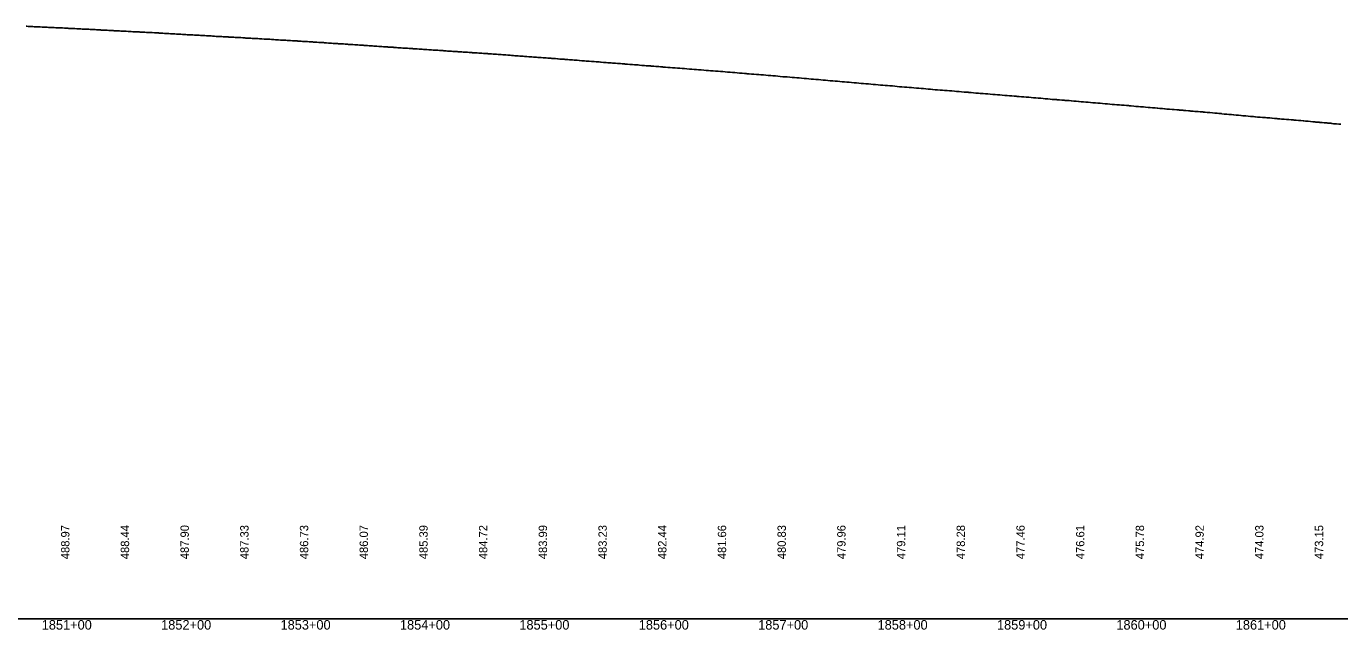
# Model space of a CAD drawing. Extents: x 2017200 to 2047700, y 854850 to 893350.
# Drawn here: x 2040063 to 2041163, y 856091 to 856597 of the extents above; entities that cross this region are included whole.
import ezdxf

# ---------------------------------------------------------------- set-up
doc = ezdxf.new("R2010")
doc.units = 0
for name, color, linetype in [('RD_DDB_Profile_EX', 7, 'Continuous'), ('RD_DDB_StaTX', 7, 'Continuous'), ('RD_DDB_StripGrade', 7, 'Continuous'), ('RD_GPK_Profile_Cell', 7, 'Continuous')]:
    doc.layers.add(name, color=color, linetype=linetype)

msp = doc.modelspace()

# ---------------------------------------------------------------- linework, layer by layer
at = {"layer": 'RD_DDB_Profile_EX'}
msp.add_lwpolyline([(2040062.7, 856596.7), (2040063.4, 856596.6), (2040064.4, 856596.5), (2040066.2, 856596.5), (2040067.6, 856596.4), (2040068.3, 856596.4), (2040069.5, 856596.3), (2040070.3, 856596.3), (2040071.3, 856596.2), (2040072.3, 856596.2), (2040072.9, 856596.2), (2040073.8, 856596.1), (2040074.6, 856596.1), (2040076.3, 856596), (2040077.7, 856595.9), (2040078.3, 856595.9), (2040079.6, 856595.8), (2040080.4, 856595.8), (2040081.4, 856595.7), (2040082.5, 856595.7), (2040083.1, 856595.7), (2040084.7, 856595.6), (2040086.3, 856595.5), (2040087.7, 856595.4), (2040088.4, 856595.4), (2040089.7, 856595.4), (2040090.5, 856595.3), (2040091.5, 856595.3), (2040092.6, 856595.2), (2040093.3, 856595.2), (2040094.8, 856595.1), (2040096.4, 856595), (2040097.8, 856595), (2040098.4, 856594.9), (2040099.7, 856594.9), (2040100.5, 856594.8), (2040101.6, 856594.8), (2040102.7, 856594.7), (2040103.5, 856594.7), (2040105.1, 856594.6), (2040106.4, 856594.5), (2040107.9, 856594.4), (2040108.5, 856594.4), (2040109.8, 856594.3), (2040110.6, 856594.3), (2040111.8, 856594.2), (2040112.7, 856594.2), (2040113.6, 856594.2), (2040115.3, 856594.1), (2040116.5, 856594), (2040117.9, 856593.9), (2040118.5, 856593.9), (2040119.9, 856593.8), (2040120.6, 856593.8), (2040121.8, 856593.7), (2040122.8, 856593.7), (2040123.7, 856593.6), (2040125.1, 856593.6), (2040125.5, 856593.5), (2040126.5, 856593.5), (2040128, 856593.4), (2040128.6, 856593.4), (2040130, 856593.3), (2040130.7, 856593.3), (2040131.9, 856593.2), (2040132.9, 856593.1), (2040133.9, 856593.1), (2040135.2, 856593), (2040135.7, 856593), (2040136.6, 856592.9), (2040138.1, 856592.8), (2040138.6, 856592.8), (2040140, 856592.7), (2040140.8, 856592.7), (2040142, 856592.6), (2040142.9, 856592.6), (2040144, 856592.5), (2040145.3, 856592.5), (2040145.9, 856592.5), (2040146.5, 856592.4), (2040148.1, 856592.3), (2040148.7, 856592.3), (2040150.1, 856592.2), (2040150.8, 856592.2), (2040152.1, 856592.1), (2040153, 856592.1), (2040154.1, 856592), (2040155.3, 856591.9), (2040156, 856591.9), (2040157.6, 856591.9), (2040158.1, 856591.8), (2040160.2, 856591.7), (2040161.6, 856591.6), (2040162.2, 856591.6), (2040163.5, 856591.5), (2040164.2, 856591.5), (2040165.3, 856591.4), (2040166.2, 856591.4), (2040166.9, 856591.3), (2040168.2, 856591.3), (2040170.2, 856591.1), (2040171.7, 856591.1), (2040172.2, 856591), (2040173.6, 856591), (2040174.2, 856590.9), (2040175.4, 856590.9), (2040176.3, 856590.8), (2040177.1, 856590.8), (2040178.5, 856590.7), (2040180.3, 856590.6), (2040181.7, 856590.5), (2040182.3, 856590.5), (2040183.7, 856590.4), (2040184.3, 856590.4), (2040185.5, 856590.3), (2040186.4, 856590.3), (2040187.3, 856590.2), (2040188.8, 856590.1), (2040190.3, 856590), (2040191.8, 856589.9), (2040192.3, 856589.9), (2040193.7, 856589.8), (2040194.4, 856589.8), (2040195.6, 856589.7), (2040196.5, 856589.7), (2040197.5, 856589.6), (2040198.6, 856589.6), (2040199, 856589.5), (2040200.3, 856589.5), (2040201.9, 856589.4), (2040202.4, 856589.4), (2040203.8, 856589.3), (2040204.4, 856589.2), (2040205.7, 856589.2), (2040206.5, 856589.1), (2040207.6, 856589.1), (2040208.7, 856589), (2040209.3, 856589), (2040210.4, 856588.9), (2040211.9, 856588.8), (2040212.4, 856588.8), (2040213.9, 856588.7), (2040214.5, 856588.7), (2040215.8, 856588.6), (2040216.6, 856588.6), (2040217.7, 856588.5), (2040218.8, 856588.4), (2040219.5, 856588.4), (2040220.4, 856588.3), (2040222, 856588.2), (2040222.5, 856588.2), (2040223.9, 856588.1), (2040224.5, 856588.1), (2040225.9, 856588), (2040226.7, 856588), (2040227.8, 856587.9), (2040228.9, 856587.8), (2040229.6, 856587.8), (2040230.4, 856587.7), (2040232, 856587.7), (2040232.5, 856587.6), (2040234, 856587.5), (2040234.6, 856587.5), (2040236, 856587.4), (2040236.7, 856587.4), (2040237.9, 856587.3), (2040239, 856587.3), (2040239.8, 856587.2), (2040240.5, 856587.2), (2040242.1, 856587.1), (2040242.5, 856587.1), (2040244.1, 856587), (2040244.6, 856586.9), (2040246, 856586.9), (2040246.7, 856586.8), (2040248, 856586.8), (2040249, 856586.7), (2040249.9, 856586.6), (2040250.9, 856586.6), (2040252.1, 856586.5), (2040252.5, 856586.5), (2040254.1, 856586.4), (2040254.6, 856586.4), (2040256.1, 856586.3), (2040256.8, 856586.3), (2040258.1, 856586.2), (2040259, 856586.1), (2040260, 856586.1), (2040262.2, 856585.9), (2040264.1, 856585.8), (2040264.7, 856585.8), (2040266.1, 856585.7), (2040266.8, 856585.7), (2040268.1, 856585.6), (2040269.1, 856585.5), (2040270.1, 856585.5), (2040271.7, 856585.4), (2040272.1, 856585.3), (2040272.6, 856585.3), (2040274.2, 856585.2), (2040275.8, 856585.1), (2040276.2, 856585.1), (2040277.7, 856585), (2040278.2, 856585), (2040279.6, 856584.9), (2040280.2, 856584.9), (2040281.4, 856584.8), (2040282.3, 856584.7), (2040282.9, 856584.7), (2040284.2, 856584.6), (2040285.8, 856584.5), (2040286.2, 856584.5), (2040287.8, 856584.4), (2040288.3, 856584.4), (2040289.7, 856584.3), (2040290.3, 856584.2), (2040291.5, 856584.2), (2040292.4, 856584.1), (2040293.1, 856584.1), (2040294.3, 856584), (2040295.9, 856583.9), (2040296.3, 856583.9), (2040297.8, 856583.8), (2040298.3, 856583.8), (2040299.7, 856583.7), (2040300.4, 856583.6), (2040301.6, 856583.6), (2040302.5, 856583.5), (2040303.3, 856583.4), (2040304.3, 856583.4), (2040305.9, 856583.3), (2040306.3, 856583.2), (2040307.9, 856583.1), (2040308.4, 856583.1), (2040309.8, 856583), (2040310.4, 856583), (2040311.7, 856582.9), (2040312.6, 856582.8), (2040313.5, 856582.8), (2040314.3, 856582.7), (2040316, 856582.6), (2040316.4, 856582.6), (2040317.9, 856582.5), (2040318.4, 856582.4), (2040319.9, 856582.3), (2040320.5, 856582.3), (2040321.8, 856582.2), (2040322.6, 856582.2), (2040323.6, 856582.1), (2040324.3, 856582), (2040326, 856581.9), (2040326.4, 856581.9), (2040328, 856581.8), (2040328.4, 856581.8), (2040329.9, 856581.7), (2040330.5, 856581.7), (2040331.9, 856581.6), (2040332.7, 856581.5), (2040333.7, 856581.4), (2040335.4, 856581.3), (2040336, 856581.3), (2040336.4, 856581.3), (2040338, 856581.1), (2040338.5, 856581.1), (2040340, 856581), (2040340.6, 856581), (2040341.9, 856580.9), (2040342.8, 856580.8), (2040343.8, 856580.8), (2040345.2, 856580.7), (2040345.6, 856580.6), (2040346.5, 856580.6), (2040348.1, 856580.5), (2040348.5, 856580.4), (2040350, 856580.3), (2040350.6, 856580.3), (2040352, 856580.2), (2040352.8, 856580.2), (2040353.9, 856580.1), (2040355.3, 856580), (2040355.8, 856580), (2040356.5, 856579.9), (2040358.1, 856579.8), (2040358.6, 856579.8), (2040360.1, 856579.6), (2040360.7, 856579.6), (2040362.1, 856579.5), (2040362.9, 856579.5), (2040364, 856579.4), (2040365.3, 856579.3), (2040366, 856579.2), (2040366.6, 856579.2), (2040368.1, 856579.1), (2040368.6, 856579.1), (2040370.1, 856579), (2040370.8, 856578.9), (2040372.1, 856578.8), (2040373, 856578.8), (2040374.1, 856578.7), (2040375.4, 856578.6), (2040376.1, 856578.6), (2040376.8, 856578.5), (2040378.2, 856578.4), (2040379.8, 856578.3), (2040380.2, 856578.3), (2040381.7, 856578.2), (2040382.2, 856578.2), (2040383.6, 856578.1), (2040384.2, 856578), (2040385.4, 856577.9), (2040386.2, 856577.9), (2040387, 856577.8), (2040388.2, 856577.8), (2040389.8, 856577.6), (2040390.2, 856577.6), (2040391.8, 856577.5), (2040392.2, 856577.5), (2040393.7, 856577.4), (2040394.3, 856577.4), (2040395.5, 856577.3), (2040396.3, 856577.2), (2040397.2, 856577.2), (2040398.3, 856577.1), (2040399.9, 856577), (2040400.3, 856577), (2040401.8, 856576.8), (2040402.3, 856576.8), (2040403.7, 856576.7), (2040404.3, 856576.7), (2040405.6, 856576.6), (2040406.4, 856576.5), (2040407.4, 856576.5), (2040408.8, 856576.4), (2040409.9, 856576.3), (2040410.3, 856576.3), (2040411.9, 856576.2), (2040412.3, 856576.1), (2040413.8, 856576), (2040414.4, 856576), (2040415.7, 856575.9), (2040416.5, 856575.9), (2040417.5, 856575.8), (2040418.7, 856575.7), (2040419.1, 856575.7), (2040420, 856575.6), (2040420.3, 856575.6), (2040421.9, 856575.5), (2040422.4, 856575.5), (2040423.9, 856575.4), (2040424.4, 856575.3), (2040425.8, 856575.3), (2040426.6, 856575.2), (2040427.7, 856575.1), (2040428.8, 856575), (2040429.3, 856575), (2040430, 856575), (2040430.4, 856574.9), (2040432, 856574.8), (2040432.4, 856574.8), (2040433.9, 856574.7), (2040434.5, 856574.7), (2040435.9, 856574.6), (2040436.6, 856574.5), (2040437.8, 856574.4), (2040438.9, 856574.4), (2040439.5, 856574.3), (2040440.4, 856574.3), (2040442, 856574.1), (2040442.5, 856574.1), (2040444, 856574), (2040444.5, 856574), (2040445.9, 856573.9), (2040446.7, 856573.8), (2040447.9, 856573.8), (2040449, 856573.7), (2040449.7, 856573.6), (2040450.4, 856573.6), (2040452.1, 856573.5), (2040452.5, 856573.5), (2040454, 856573.3), (2040454.6, 856573.3), (2040456, 856573.2), (2040456.7, 856573.2), (2040458, 856573), (2040459, 856573), (2040459.8, 856572.9), (2040460.5, 856572.9), (2040462.1, 856572.7), (2040462.5, 856572.7), (2040464.1, 856572.6), (2040464.6, 856572.6), (2040466.1, 856572.4), (2040466.8, 856572.4), (2040468, 856572.3), (2040469.1, 856572.2), (2040470, 856572.2), (2040470.9, 856572.1), (2040472.1, 856572), (2040472.6, 856572), (2040474.1, 856571.8), (2040474.7, 856571.8), (2040476.1, 856571.7), (2040476.8, 856571.7), (2040478.1, 856571.6), (2040479.1, 856571.5), (2040480.1, 856571.4), (2040481.1, 856571.4), (2040482.2, 856571.3), (2040483.8, 856571.1), (2040484.2, 856571.1), (2040485.8, 856571), (2040486.2, 856571), (2040487.7, 856570.8), (2040488.2, 856570.8), (2040489.5, 856570.7), (2040490.2, 856570.7), (2040491.3, 856570.6), (2040492.2, 856570.5), (2040493.9, 856570.4), (2040494.2, 856570.4), (2040495.8, 856570.2), (2040496.2, 856570.2), (2040497.8, 856570.1), (2040498.2, 856570.1), (2040499.6, 856570), (2040500.3, 856569.9), (2040501.4, 856569.8), (2040502.3, 856569.8), (2040502.9, 856569.7), (2040503.9, 856569.6), (2040504.2, 856569.6), (2040505.9, 856569.5), (2040506.2, 856569.5), (2040507.8, 856569.4), (2040508.3, 856569.3), (2040509.7, 856569.2), (2040510.3, 856569.2), (2040511.6, 856569.1), (2040512.4, 856569), (2040513.2, 856569), (2040514.3, 856568.9), (2040515.9, 856568.8), (2040516.3, 856568.7), (2040517.9, 856568.6), (2040518.3, 856568.6), (2040519.8, 856568.5), (2040520.4, 856568.4), (2040521.7, 856568.3), (2040522.5, 856568.3), (2040523.4, 856568.2), (2040524.3, 856568.1), (2040526, 856568), (2040526.3, 856568), (2040528, 856567.8), (2040528.3, 856567.8), (2040529.9, 856567.7), (2040530.4, 856567.7), (2040531.8, 856567.5), (2040532.6, 856567.5), (2040533.6, 856567.4), (2040534.3, 856567.4), (2040536.3, 856567.2), (2040538, 856567.1), (2040538.4, 856567), (2040540, 856566.9), (2040540.4, 856566.9), (2040541.9, 856566.8), (2040542.6, 856566.7), (2040543.7, 856566.6), (2040544.3, 856566.6), (2040546.3, 856566.4), (2040548, 856566.3), (2040548.4, 856566.3), (2040550, 856566.1), (2040550.4, 856566.1), (2040552, 856566), (2040552.6, 856565.9), (2040553.9, 856565.8), (2040554.3, 856565.8), (2040556.3, 856565.7), (2040558.1, 856565.5), (2040558.4, 856565.5), (2040560.1, 856565.4), (2040560.5, 856565.4), (2040562, 856565.2), (2040562.6, 856565.2), (2040564, 856565.1), (2040564.3, 856565), (2040566.3, 856564.9), (2040568.4, 856564.7), (2040570.1, 856564.6), (2040570.5, 856564.6), (2040572.1, 856564.4), (2040572.6, 856564.4), (2040574, 856564.3), (2040575.4, 856564.2), (2040576.4, 856564.1), (2040578.4, 856563.9), (2040580.1, 856563.8), (2040580.5, 856563.8), (2040582.1, 856563.6), (2040582.6, 856563.6), (2040584.1, 856563.5), (2040585.6, 856563.4), (2040586.1, 856563.3), (2040588.4, 856563.1), (2040590.1, 856563), (2040590.5, 856563), (2040592.1, 856562.9), (2040592.6, 856562.8), (2040594.1, 856562.7), (2040595.7, 856562.6), (2040596.2, 856562.5), (2040598.2, 856562.4), (2040600.2, 856562.2), (2040602.2, 856562.1), (2040604.2, 856561.9), (2040605.8, 856561.8), (2040606.2, 856561.8), (2040608.2, 856561.6), (2040610.2, 856561.4), (2040612.2, 856561.3), (2040614.2, 856561.2), (2040616.2, 856561), (2040618.2, 856560.8), (2040620.2, 856560.7), (2040622.2, 856560.5), (2040624.2, 856560.3), (2040625.9, 856560.2), (2040626.3, 856560.2), (2040627.7, 856560), (2040628.2, 856560), (2040630.2, 856559.9), (2040632.2, 856559.7), (2040634.3, 856559.5), (2040636, 856559.4), (2040636.4, 856559.4), (2040638.2, 856559.2), (2040640.2, 856559.1), (2040642.2, 856558.9), (2040644.3, 856558.8), (2040646, 856558.6), (2040646.3, 856558.6), (2040648.2, 856558.4), (2040650.2, 856558.3), (2040652.3, 856558.1), (2040654.3, 856557.9), (2040656, 856557.8), (2040656.4, 856557.8), (2040658.2, 856557.6), (2040660.3, 856557.4), (2040662.3, 856557.3), (2040664.3, 856557.1), (2040666.1, 856557), (2040666.4, 856556.9), (2040668.3, 856556.8), (2040670.3, 856556.6), (2040672.3, 856556.4), (2040674.3, 856556.3), (2040676.4, 856556.1), (2040678.1, 856556), (2040679.8, 856555.8), (2040680.2, 856555.8), (2040682.3, 856555.6), (2040684.3, 856555.4), (2040686.4, 856555.3), (2040688.1, 856555.1), (2040690.3, 856555), (2040692.3, 856554.8), (2040694.3, 856554.6), (2040696.4, 856554.4), (2040698.1, 856554.3), (2040700.2, 856554.2), (2040702.2, 856554), (2040704.2, 856553.8), (2040706.2, 856553.6), (2040708.2, 856553.5), (2040710.2, 856553.3), (2040712.2, 856553.1), (2040714.2, 856552.9), (2040716.2, 856552.8), (2040718.2, 856552.6), (2040720.2, 856552.4), (2040722.2, 856552.3), (2040724.2, 856552.1), (2040726.2, 856551.9), (2040728.2, 856551.7), (2040730.2, 856551.6), (2040732.2, 856551.4), (2040734.2, 856551.2), (2040736.2, 856551), (2040738.2, 856550.9), (2040740.2, 856550.7), (2040742.2, 856550.5), (2040744.2, 856550.4), (2040746.1, 856550.2), (2040748.1, 856550), (2040750.1, 856549.8), (2040752.1, 856549.7), (2040754.1, 856549.5), (2040756.1, 856549.3), (2040758.2, 856549.1), (2040760.1, 856549), (2040762.1, 856548.8), (2040764.1, 856548.6), (2040766.1, 856548.5), (2040768.1, 856548.3), (2040770.1, 856548.1), (2040772.2, 856547.9), (2040774.2, 856547.7), (2040776.2, 856547.6), (2040778.2, 856547.4), (2040780.2, 856547.2), (2040782.2, 856547.1), (2040784.2, 856546.9), (2040786.2, 856546.7), (2040788.2, 856546.6), (2040790.2, 856546.4), (2040792.2, 856546.2), (2040794.2, 856546), (2040796.2, 856545.9), (2040798.3, 856545.7), (2040800.3, 856545.5), (2040802.2, 856545.4), (2040804.2, 856545.2), (2040806.2, 856545.1), (2040808.4, 856544.9), (2040810.3, 856544.7), (2040812.3, 856544.5), (2040814.2, 856544.4), (2040816.2, 856544.2), (2040818.1, 856544), (2040818.4, 856544), (2040820.1, 856543.9), (2040821.8, 856543.7), (2040822.1, 856543.7), (2040824.1, 856543.5), (2040826.1, 856543.4), (2040828.1, 856543.2), (2040828.6, 856543.2), (2040830.2, 856543), (2040831.8, 856542.9), (2040832.2, 856542.9), (2040834.2, 856542.7), (2040836.1, 856542.5), (2040838.1, 856542.4), (2040840.2, 856542.2), (2040841.8, 856542.1), (2040842.2, 856542), (2040844.2, 856541.9), (2040846.2, 856541.7), (2040848.2, 856541.5), (2040850.3, 856541.4), (2040851.8, 856541.3), (2040852.2, 856541.2), (2040854.2, 856541), (2040856.2, 856540.9), (2040858.2, 856540.7), (2040860.4, 856540.5), (2040861.8, 856540.4), (2040862.3, 856540.4), (2040864.2, 856540.2), (2040866.2, 856540.1), (2040868.2, 856539.9), (2040870.2, 856539.7), (2040872.3, 856539.5), (2040874.3, 856539.4), (2040876.2, 856539.2), (2040878.2, 856539.1), (2040880.2, 856538.9), (2040882.4, 856538.7), (2040884.3, 856538.6), (2040886.2, 856538.4), (2040888.2, 856538.3), (2040890.2, 856538.1), (2040892.1, 856538), (2040892.4, 856537.9), (2040894, 856537.8), (2040894.3, 856537.7), (2040896.3, 856537.6), (2040898.2, 856537.4), (2040900.2, 856537.3), (2040902.1, 856537.1), (2040902.5, 856537.1), (2040904.4, 856536.9), (2040906.3, 856536.8), (2040908.3, 856536.6), (2040910.2, 856536.5), (2040912.1, 856536.3), (2040912.5, 856536.3), (2040914.4, 856536.1), (2040916.3, 856535.9), (2040918.3, 856535.8), (2040920.3, 856535.6), (2040922.1, 856535.4), (2040922.6, 856535.4), (2040924.1, 856535.3), (2040925.6, 856535.2), (2040926.1, 856535.1), (2040927.8, 856535), (2040928.1, 856534.9), (2040930.1, 856534.8), (2040932.1, 856534.6), (2040932.8, 856534.5), (2040934.2, 856534.4), (2040935.6, 856534.3), (2040936.2, 856534.3), (2040937.8, 856534.1), (2040938.2, 856534.1), (2040940.2, 856533.9), (2040942.1, 856533.8), (2040944.1, 856533.6), (2040944.5, 856533.6), (2040946.2, 856533.4), (2040948.2, 856533.2), (2040950.2, 856533.1), (2040952.2, 856532.9), (2040954.2, 856532.8), (2040956.2, 856532.6), (2040957.9, 856532.4), (2040958.2, 856532.4), (2040960.2, 856532.2), (2040962.2, 856532.1), (2040964.2, 856531.9), (2040966.3, 856531.7), (2040967.9, 856531.6), (2040968.3, 856531.6), (2040970.2, 856531.4), (2040972.2, 856531.2), (2040974.2, 856531.1), (2040976.3, 856530.9), (2040977.9, 856530.8), (2040978.3, 856530.7), (2040980.2, 856530.5), (2040982.2, 856530.4), (2040984.2, 856530.2), (2040986.1, 856530.1), (2040986.4, 856530), (2040987.9, 856529.9), (2040988.3, 856529.9), (2040990.3, 856529.7), (2040992.2, 856529.5), (2040994.2, 856529.4), (2040996.1, 856529.2), (2040996.5, 856529.2), (2040998, 856529), (2040998.4, 856529), (2041000.3, 856528.9), (2041002.3, 856528.7), (2041004.2, 856528.5), (2041006.1, 856528.4), (2041006.6, 856528.3), (2041008, 856528.2), (2041008.4, 856528.2), (2041010.1, 856528), (2041010.4, 856528), (2041012.3, 856527.8), (2041014.3, 856527.7), (2041016.1, 856527.5), (2041016.8, 856527.5), (2041018.1, 856527.3), (2041018.5, 856527.3), (2041020.1, 856527.2), (2041020.4, 856527.1), (2041022.4, 856527), (2041024.3, 856526.8), (2041026.3, 856526.7), (2041028.1, 856526.5), (2041028.6, 856526.4), (2041030.1, 856526.3), (2041031.6, 856526.2), (2041032.1, 856526.1), (2041033.8, 856526), (2041034.1, 856526), (2041036.1, 856525.8), (2041037.3, 856525.7), (2041038.2, 856525.6), (2041039.2, 856525.5), (2041040.2, 856525.4), (2041041.6, 856525.3), (2041042.2, 856525.3), (2041043.8, 856525.1), (2041044.2, 856525.1), (2041046.1, 856524.9), (2041048.1, 856524.8), (2041048.8, 856524.7), (2041050.2, 856524.6), (2041051.7, 856524.5), (2041052.2, 856524.4), (2041053.8, 856524.3), (2041054.2, 856524.3), (2041056.2, 856524.1), (2041058.2, 856523.9), (2041060, 856523.7), (2041060.3, 856523.7), (2041061.7, 856523.6), (2041062.2, 856523.5), (2041063.9, 856523.4), (2041064.2, 856523.3), (2041066.2, 856523.1), (2041068.2, 856523), (2041070, 856522.8), (2041070.3, 856522.8), (2041071.8, 856522.6), (2041072.3, 856522.6), (2041073.9, 856522.4), (2041074.2, 856522.4), (2041076.2, 856522.2), (2041078.2, 856522), (2041080, 856521.9), (2041080.4, 856521.8), (2041081.8, 856521.7), (2041082.3, 856521.6), (2041083.9, 856521.5), (2041084.3, 856521.5), (2041086.2, 856521.3), (2041088.2, 856521.1), (2041090.2, 856521), (2041090.6, 856520.9), (2041091.8, 856520.8), (2041092.4, 856520.8), (2041093.9, 856520.6), (2041094.3, 856520.6), (2041096.3, 856520.4), (2041098.3, 856520.3), (2041100.2, 856520.1), (2041100.7, 856520.1), (2041101.8, 856520), (2041102.5, 856519.9), (2041104, 856519.8), (2041104.4, 856519.8), (2041106, 856519.6), (2041106.3, 856519.6), (2041108.3, 856519.4), (2041110.3, 856519.3), (2041110.9, 856519.2), (2041111.9, 856519.1), (2041112.6, 856519.1), (2041114, 856518.9), (2041114.4, 856518.9), (2041116, 856518.8), (2041116.4, 856518.7), (2041118.3, 856518.6), (2041120.3, 856518.4), (2041122.1, 856518.3), (2041122.6, 856518.2), (2041124.1, 856518.1), (2041124.5, 856518), (2041126.1, 856517.9), (2041126.4, 856517.9), (2041128.3, 856517.7), (2041130.3, 856517.6), (2041132.1, 856517.4), (2041132.7, 856517.3), (2041134.1, 856517.2), (2041134.5, 856517.2), (2041136.4, 856517), (2041138.3, 856516.8), (2041140.3, 856516.6), (2041142.1, 856516.5), (2041142.8, 856516.4), (2041144.2, 856516.3), (2041145.5, 856516.2), (2041146.2, 856516.1), (2041147.7, 856516), (2041148.2, 856515.9), (2041149.8, 856515.8), (2041150.1, 856515.7), (2041152.1, 856515.6), (2041153, 856515.5), (2041154.3, 856515.4), (2041155.5, 856515.3), (2041156.2, 856515.2), (2041157.7, 856515), (2041158.2, 856515), (2041159.8, 856514.9), (2041160.2, 856514.8), (2041162.2, 856514.6), (2041163.9, 856514.5)], dxfattribs=at)
at = {"layer": 'RD_GPK_Profile_Cell'}
msp.add_line((2020500, 856100), (2047700, 856100), dxfattribs=at)

# ---------------------------------------------------------------- texts
at = {"layer": 'RD_DDB_StaTX'}
for s, p in [('1851+00', (2040075.8, 856091)), ('1852+00', (2040175.8, 856091)), ('1853+00', (2040275.8, 856091)), ('1854+00', (2040375.8, 856091)), ('1855+00', (2040475.8, 856091)), ('1856+00', (2040575.8, 856091)), ('1857+00', (2040675.8, 856091)), ('1858+00', (2040775.8, 856091)), ('1859+00', (2040875.8, 856091)), ('1860+00', (2040975.8, 856091)), ('1861+00', (2041075.8, 856091))]:
    msp.add_text(s, height=8, dxfattribs=at).set_placement(p)
at = {"layer": 'RD_DDB_StripGrade'}
for s, p in [('488.97', (2040099, 856150)), ('488.44', (2040149, 856150)), ('487.90', (2040199, 856150)), ('487.33', (2040249, 856150)), ('486.73', (2040299, 856150)), ('486.07', (2040349, 856150)), ('485.39', (2040399, 856150)), ('484.72', (2040449, 856150)), ('483.99', (2040499, 856150)), ('483.23', (2040549, 856150)), ('482.44', (2040599, 856150)), ('481.66', (2040649, 856150)), ('480.83', (2040699, 856150)), ('479.96', (2040749, 856150)), ('479.11', (2040799, 856150)), ('478.28', (2040849, 856150)), ('477.46', (2040899, 856150)), ('476.61', (2040949, 856150)), ('475.78', (2040999, 856150)), ('474.92', (2041049, 856150)), ('474.03', (2041099, 856150)), ('473.15', (2041149, 856150))]:
    msp.add_text(s, height=7, rotation=90, dxfattribs=at).set_placement(p)

doc.saveas('drawing.dxf')
